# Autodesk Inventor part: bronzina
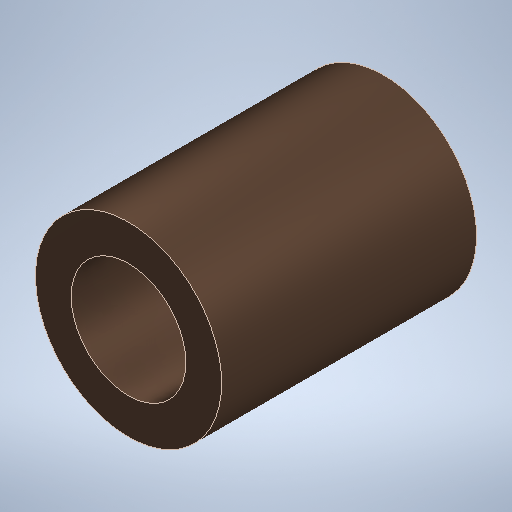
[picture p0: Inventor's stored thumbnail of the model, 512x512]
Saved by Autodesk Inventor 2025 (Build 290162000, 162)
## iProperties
Created: 2025-10
Part Number: bronzina
Material: Generico
Document SubType Name: Modeling
Designer: 18619647
Density: 1 g/cm^3
Appearance: Bronzo - Satinato
Author: 18619647
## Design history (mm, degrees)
sketch "Schizzo2"
  geometry: C1 r 6.5 at (0, 0); C2 r 4 at (0, 0); 1 further point
  constraints: 2 centre point, 2 coincident
  dimensions: "d4" = 13 diameter of C1; "d5" = 8 diameter of C2
extrude "Estrusione2" new body sketch "Schizzo2" distance "d6" = 17.8; taper "d7" = 0 deg
node "Solido2"
